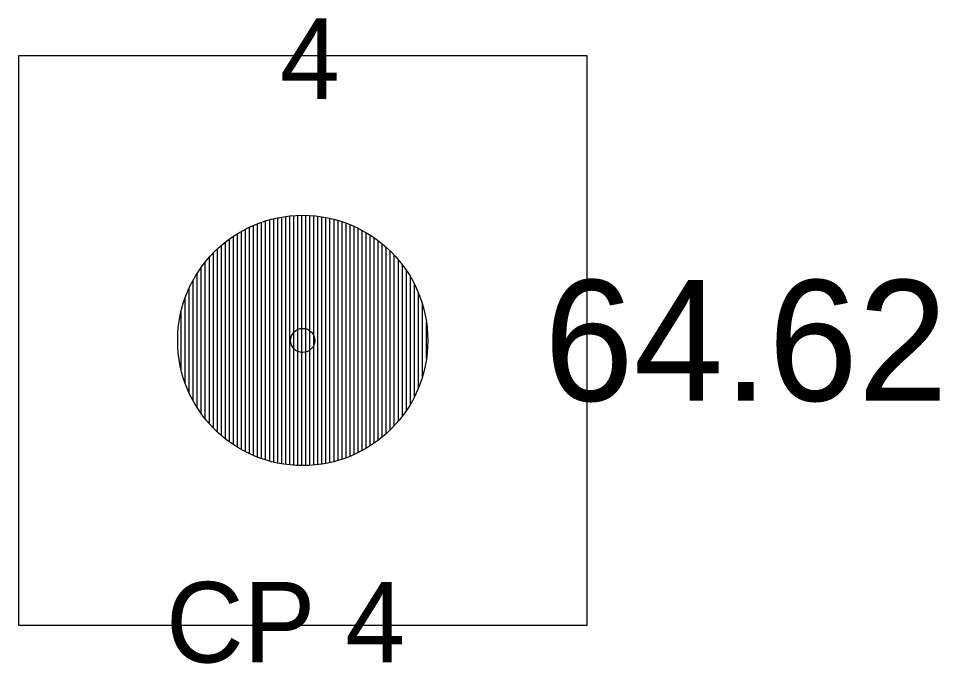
# Model space of a CAD drawing. Extents: x 2420113 to 2422887, y 845323 to 846653.
# Drawn here: x 2422875.55 to 2422887, y 846644.56 to 846652.58 of the extents above; entities that cross this region are included whole.
import ezdxf

# ---------------------------------------------------------------- set-up
doc = ezdxf.new("R2010")
doc.units = 0
for name, color, linetype in [('RD_HC_Survey', 7, 'Continuous'), ('RD_HC_Survey_ELEV', 7, 'Continuous'), ('RD_HC_Survey_txCode', 7, 'Continuous'), ('RD_SMD_Locator', 7, 'Continuous')]:
    doc.layers.add(name, color=color, linetype=linetype)

msp = doc.modelspace()

# ---------------------------------------------------------------- linework, layer by layer
at = {"layer": 'RD_HC_Survey'}
for p, q in [((2422878.673, 846647.079), (2422878.673, 846650.077)), ((2422878.723, 846647.066), (2422878.723, 846650.09)), ((2422878.773, 846647.055), (2422878.773, 846650.101)), ((2422878.823, 846647.046), (2422878.823, 846650.111)), ((2422878.873, 846647.038), (2422878.873, 846650.118)), ((2422878.923, 846647.032), (2422878.923, 846650.124)), ((2422878.973, 846647.028), (2422878.973, 846650.129)), ((2422879.023, 846647.025), (2422879.023, 846650.132)), ((2422879.073, 846647.024), (2422879.073, 846650.133)), ((2422879.123, 846647.024), (2422879.123, 846650.132)), ((2422879.173, 846647.026), (2422879.173, 846650.13)), ((2422879.223, 846647.03), (2422879.223, 846650.127)), ((2422879.273, 846647.035), (2422879.273, 846650.121)), ((2422879.323, 846647.042), (2422879.323, 846650.115)), ((2422879.373, 846647.051), (2422879.373, 846650.106)), ((2422879.423, 846647.061), (2422879.423, 846650.096)), ((2422879.473, 846647.073), (2422879.473, 846650.084)), ((2422878.373, 846647.196), (2422878.373, 846649.96)), ((2422878.423, 846647.172), (2422878.423, 846649.985)), ((2422878.473, 846647.149), (2422878.473, 846650.007)), ((2422878.523, 846647.129), (2422878.523, 846650.028)), ((2422878.573, 846647.11), (2422878.573, 846650.046)), ((2422878.623, 846647.094), (2422878.623, 846650.063)), ((2422879.523, 846647.087), (2422879.523, 846650.07)), ((2422879.573, 846647.102), (2422879.573, 846650.054)), ((2422879.623, 846647.12), (2422879.623, 846650.037)), ((2422879.673, 846647.139), (2422879.673, 846650.017)), ((2422879.723, 846647.161), (2422879.723, 846649.996)), ((2422879.773, 846647.184), (2422879.773, 846649.972)), ((2422878.223, 846647.285), (2422878.223, 846649.872)), ((2422878.273, 846647.253), (2422878.273, 846649.904)), ((2422878.323, 846647.223), (2422878.323, 846649.933)), ((2422879.823, 846647.21), (2422879.823, 846649.946)), ((2422879.873, 846647.238), (2422879.873, 846649.918)), ((2422879.923, 846647.269), (2422879.923, 846649.888)), ((2422879.973, 846647.302), (2422879.973, 846649.854)), ((2422878.073, 846647.398), (2422878.073, 846649.758)), ((2422878.123, 846647.357), (2422878.123, 846649.8)), ((2422878.173, 846647.319), (2422878.173, 846649.837)), ((2422880.023, 846647.339), (2422880.023, 846649.818)), ((2422880.073, 846647.378), (2422880.073, 846649.778)), ((2422880.123, 846647.421), (2422880.123, 846649.735)), ((2422877.973, 846647.492), (2422877.973, 846649.665)), ((2422878.023, 846647.443), (2422878.023, 846649.714)), ((2422880.173, 846647.468), (2422880.173, 846649.689)), ((2422880.223, 846647.519), (2422880.223, 846649.637)), ((2422877.873, 846647.605), (2422877.873, 846649.552)), ((2422877.923, 846647.545), (2422877.923, 846649.611)), ((2422880.273, 846647.576), (2422880.273, 846649.581)), ((2422880.323, 846647.638), (2422880.323, 846649.518)), ((2422877.773, 846647.744), (2422877.773, 846649.412)), ((2422877.823, 846647.67), (2422877.823, 846649.486)), ((2422880.373, 846647.708), (2422880.373, 846649.449)), ((2422877.723, 846647.829), (2422877.723, 846649.328)), ((2422880.423, 846647.787), (2422880.423, 846649.37)), ((2422880.473, 846647.878), (2422880.473, 846649.278)), ((2422877.673, 846647.928), (2422877.673, 846649.229)), ((2422880.523, 846647.988), (2422880.523, 846649.169)), ((2422877.623, 846648.05), (2422877.623, 846649.107)), ((2422877.573, 846648.216), (2422877.573, 846648.94)), ((2422880.573, 846648.129), (2422880.573, 846649.028)), ((2422880.623, 846648.352), (2422880.623, 846648.804))]:
    msp.add_line(p, q, dxfattribs=at)
msp.add_lwpolyline([(2422882.62, 846652.114), (2422875.549, 846652.114), (2422875.549, 846645.043), (2422882.62, 846645.043)], close=True, dxfattribs=at)
msp.add_circle((2422879.084, 846648.578), 1.555, dxfattribs=at)
at = {"layer": 'RD_SMD_Locator'}
msp.add_circle((2422879.084, 846648.578), 0.15, dxfattribs=at)

# ---------------------------------------------------------------- texts
at = {"layer": 'RD_HC_Survey_ELEV'}
msp.add_text('64.62', height=1.5, dxfattribs=at).set_placement((2422882.084, 846647.828))
at = {"layer": 'RD_HC_Survey_txCode'}
for s, p in [('4', (2422878.801, 846651.578)), ('CP 4', (2422877.384, 846644.578))]:
    msp.add_text(s, height=1, dxfattribs=at).set_placement(p)

doc.saveas('drawing.dxf')
